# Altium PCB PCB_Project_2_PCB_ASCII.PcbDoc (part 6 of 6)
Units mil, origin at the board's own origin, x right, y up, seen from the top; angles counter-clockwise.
Board outline 3900 x 7800 mil, 6 copper layers (Top Layer, GND 1, Signal, Power, GND 2, Bottom Layer), stack 62.1 mil thick; 636 components, 334 nets, 1830 pads, 1401 vias.
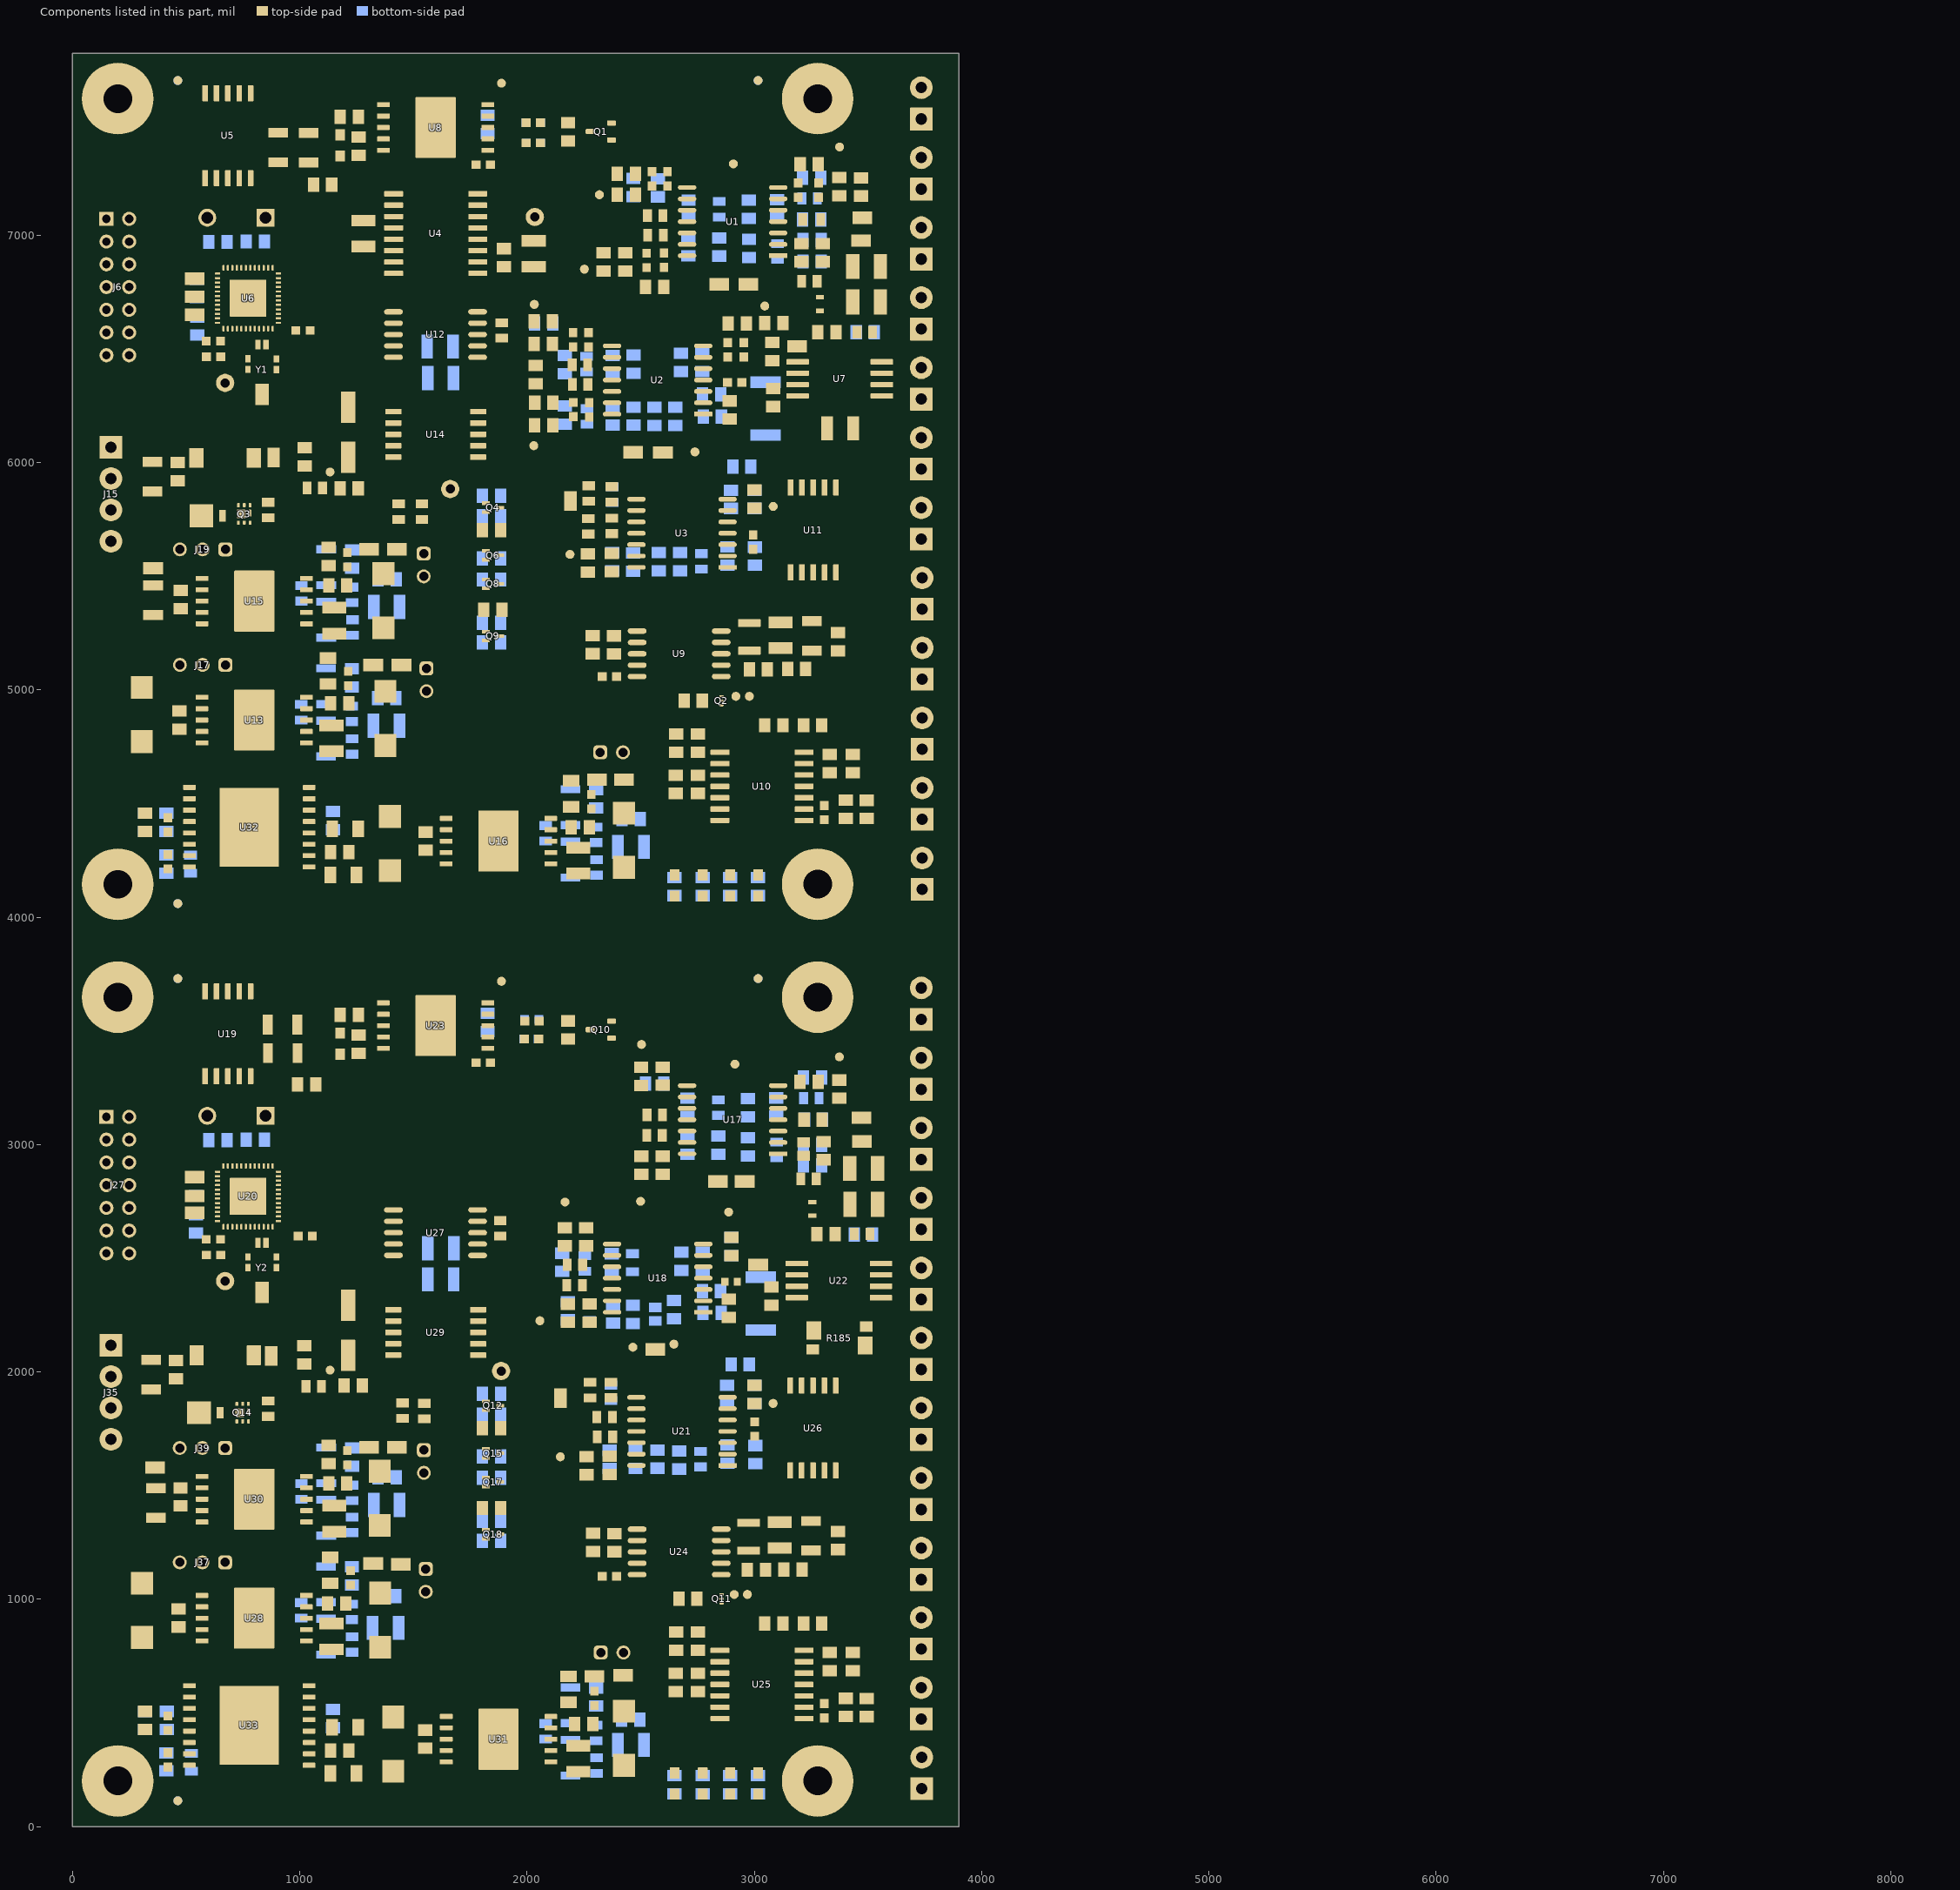
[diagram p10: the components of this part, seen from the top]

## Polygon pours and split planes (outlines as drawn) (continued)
Vcc(m) on Bottom Layer "Bottom Layer-Vcc(m) 1" (solid, pour order 1098): 2824,2077 2916,2077 2929,2064 2929,1997 2918,1986 2819,1986 2801,2004 2801,2063 2815,2077
P5V0(m) on Bottom Layer "Bottom Layer-P5V0(m)" (solid, pour order 1102): 2842.73,1627.66 2917.09,1627.66 2938.43,1606.32 2938.43,1521.93 2919.5,1503 2858.08,1503 2830.6,1530.49 2830.6,1614.29 2842.73,1626.42
Vcc(m) on Bottom Layer "Bottom Layer-Vcc(m)" (solid, pour order 1104): 2487.71,992.4 2395.34,992.4 2362.82,1024.92 2362.82,1149.9 2432.65,1219.73 2432.65,1503.07 2432.65,1593.56 2445.41,1606.32 2507.48,1606.32 2518.65,1595.16 2518.65,1505.64 2518.65,1023.34
P3V3(m) on Bottom Layer "Bottom Layer-P3V3 2" (solid, pour order 1052): 586.6,2826.86 501.86,2826.87 494.62,2834.1 494.62,2877.67 494.62,3053.31 510.22,3068.91 619.5,3068.91 634.24,3054.16 634.24,2977.38 593.41,2936.55 593.41,2887.73 593.41,2833.67
Vcc(x) on Bottom Layer "Bottom Layer-Vcc(x)" (solid, pour order 1132): 788.45,5772.8 1396.38,5772.8 1418.04,5751.13 1418.04,5693.51 1390.91,5666.37 722.72,5666.37 515.64,5873.46 113.54,5873.46 98,5889 98,5969 120,5991 568.54,5991
P2V5 on Bottom Layer "Bottom Layer-P2V5" (solid, pour order 1110): 73 vertices, not listed, extent 861.42,2272.65 3524.98,3584.86
GND on Bottom Layer "GND-GND" (solid, pour order 1152): 12.86,7692.78 12.86,4052.5 96.94,3968.42 3774.01,3968.42 3875.54,4069.96 3875.54,7746.23 3830.41,7791.36 111.44,7791.36
GND(m) on Bottom Layer "GND-GND(m)" (solid, pour order 1154): 31.47,3788.16 78.87,3835.56 3850.05,3835.56 3888.03,3797.58 3888.03,72.55 3835.6,20.12 61.99,20.12 31.47,50.64
Vee(x) on Signal "Layer 3-Vee(x)" (solid, pour order 560): 1774.99,5403.31 1803.7,5374.6 1803.7,5191.52 1773.84,5161.92 94.24,5161.92 68.43,5187.72 68.43,5812.15 108.48,5852.19 546.99,5852.19 995.87,5403.31
Vcc on Signal "Layer 3-Vcc" (solid, pour order 556): 21 vertices, not listed, extent 1888.24,5262.46 2977.65,6462.45
Vcc(m) on Signal "Layer 3-Vcc" (solid, pour order 1082): 19 vertices, not listed, extent 1888.02,1318.59 2975.15,2483.07
Vee(mx) on Signal "Layer 3-Vee(x)" (solid, pour order 1084): 1782.47,1245.54 1742.87,1204.16 105.58,1204.16 53.79,1255.95 53.79,1861.06 93.84,1901.1 532.35,1901.1 981.23,1452.22 1721.48,1452.22 1782.47,1391.24
P5V0(m,Op) on Signal "Layer 3-P5V0(Op)" (solid, pour order 1080): 26 vertices, not listed, extent 1048.23,110.66 3640.82,3182.43
P5V0(Op) on Signal "Layer 3-P5V0(Op)" (solid, pour order 558): 26 vertices, not listed, extent 1048.54,4046.74 3641.13,7156.11
NetC12_1 on Power "Power-NetC11_1" (solid, pour order 1142): 936.31,7252.76 1008.89,7252.75 1036.05,7225.6 1036.05,6631.27 1006.59,6601.81 923.66,6601.81 897.3,6628.17 897.3,7213.75
Vee(m) on Power "Layer 4-Vee" (solid, pour order 1062): 2486.32,3189.34 2514.41,3161.25 2514.41,3012.02 2514.41,2866.28 2338.8,2690.68 2338.8,1285.61 2285.7,1232.51 1955.79,1232.51 1913.36,1274.95 1913.36,2966 2136.69,3189.34
P5V0(m) on Power "Layer 4-P5V0" (solid, pour order 1066): 18 vertices, not listed, extent 75.36,115.67 3509.31,2195.26
P3V3(b) on Power "Layer 4-P3V3(b)" (solid, pour order 566): 20 vertices, not listed, extent 1087.53,4568.07 2365.95,7248.25
P3V3 on Power "Layer 4-P3V3" (solid, pour order 562): 23 vertices, not listed, extent 195.4,4770 1945.89,7617.97
P3V3(mb) on Power "Layer 4-P3V3(b)" (solid, pour order 1064): 19 vertices, not listed, extent 1032.29,623.58 2365.95,3283.28
P5V0 on Power "Layer 4-P5V0" (solid, pour order 568): 19 vertices, not listed, extent 75.36,4056.12 3499.49,6948.59
Vee on Power "Layer 4-Vee" (solid, pour order 564): 2489.91,7044.58 2516.15,7018.34 2516.15,6890.35 2358,6732.19 2358,5732.32 2358.99,5731.32 2358.99,5225.05 2310.95,5177 1955.79,5177 1916.33,5216.47 1916.33,6893.83 2067.08,7044.58
P3V3(m) on Power "Layer 4-P3V3" (solid, pour order 1068): 21 vertices, not listed, extent 202.03,807.46 1952.52,3672.39
GND on GND 1 "GND-GND" (solid, pour order 548): 12.86,7692.78 12.86,4052.5 95.35,3970.01 3775.6,3970.01 3875.54,4069.96 3875.54,7746.23 3830.41,7791.36 111.44,7791.36
GND(m) on GND 1 "GND-GND(m)" (solid, pour order 1078): 31.47,3788.16 78.87,3835.56 3850.05,3835.56 3888.03,3797.58 3888.03,72.55 3835.6,20.12 61.99,20.12 31.47,50.64
GND on GND 2 "VCC-GND" (solid, pour order 570): 108.49,7787.04 12.86,7691.41 12.86,4052.5 95.71,3969.65 3775.24,3969.65 3875.54,4069.96 3875.54,7746.23 3830.41,7791.36 113.92,7791.36 111.22,7788.66
GND(m) on GND 2 "GND-GND(m)" (solid, pour order 1108): 31.47,3788.16 78.87,3835.56 3850.05,3835.56 3888.03,3797.58 3888.03,72.55 3835.6,20.12 61.99,20.12 31.47,50.64

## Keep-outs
Keep-Out Layer:
  text ".Layer_Name" at 577,-858.49 h60

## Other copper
Top Layer:
  text ".Layer_Name" at 577,-858.49 h60
Signal:
  text "Signal layer" at 723.95,-842.08 h60
Power:
  text "Power layer" at 807.51,-851.37 h60
GND 1:
  text "GND1" at 689.91,-851.37 h60
GND 2:
  text "GND 2" at 717.76,-851.37 h60
Bottom Layer:
  text ".Layer_Name" at 577,-858.49 h60

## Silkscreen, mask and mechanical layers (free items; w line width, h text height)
Top Overlay:
  lines w10: 1187.8,7229.5 1187.8,7258.04 1311.08,7258.04 1311.08,7352.78 ; 7.49,370.03 376.46,370.03 376.46,152.55 2542.49,152.55 2542.49,923.06 1982.35,923.06 1982.35,1940 1360,1940 1360,2380.24 1058.28,2380.24 1058.28,2249.31 7.49,2249.31 7.49,370.03 ; 7.62,4318.98 7.62,6201.26 1057.97,6201.26 1057.97,6332.19 1365,6332.19 1365,5960 1944.19,5960 1944.19,4871.11 2542.62,4871.11 2542.62,4099.24 372.91,4099.24 372.91,4318.98 7.62,4318.98 ; 1205.5,6747.43 2121.46,6747.43 2121.46,7238.18 1205.5,7238.18 1205.5,6747.43 ; 1962.91,4895.89 3623.03,4895.89 3623.03,7430.32 2442.77,7430.32 2442.77,7326.58 2139.26,7326.58 2139.26,7237.19 2139.26,6728.46 1962.91,6728.46 1962.91,4895.89 ; 2002.48,943.94 2002.48,2824.35 2434.93,2824.35 2434.93,3216.03 2434.93,3362.21 2434.93,3477.3 3616.95,3477.3 3616.95,943.94 2002.48,943.94
  text "TMP461" at 1497.66,7642.24 h60
  text "D-" at 3539.41,7586.93 h60
  text "D+" at 3539.41,7517.24 h60
  text "20V" at 3559.77,7366.37 h60 r270
  text "SIGNAL CHAIN" at 2507.14,7351.52 h100
  text "U1 Out" at 2955,7302.26 h60
  text "GND" at 3561.35,7255.58 h60 r270
  text "1.TDO" at 388.38,7237.05 h60
  text "3.TDI" at 388.38,7171.18 h60
  text "500uA" at 3535.38,7109.04 h60 r270
  text "4.P3V3" at 388.38,7105.3 h60
  text "5.TMS" at 388.38,7039.42 h60
  text "7.TCk" at 388.38,6973.49 h60
  text "9.GND" at 388.38,6907.67 h60
  text "MSP430FR5969" at 570.23,6896.66 h60
  text "ADC128S102" at 1467.65,6758.39 h60
  text "DAC121S101" at 1466.7,6367.48 h60
  text "+/-5V" at 3475.44,6172.47 h60
  text "+/-2A X" at 3411.33,6012.39 h60
  text "+/-2A Y" at 3412.07,5953.3 h60
  text "Current" at 3402.53,5786.95 h40
  text "Sense Bus" at 3402.53,5749.84 h40
  text "Current" at 3402.53,5681.62 h40
  text "Sense Load" at 3402.53,5642.09 h40
  text "Vcc(y)" at 1618.87,5637.76 h60 r270
  text "1.P5V0" at 47.51,5495.69 h60
  text "40V" at 3504.58,5465.64 h60
  text "2.Vcc(x)" at 47.51,5414.26 h60
  text "GND" at 3484.07,5328.83 h60
  text "3.Vee(x)" at 47.51,5322.23 h60
  text "4.GND" at 47.51,5219.59 h60
  text "P3V3" at 1504.54,5164.07 h60
  text "5V" at 3535.72,5160.09 h60
  text "GND" at 3488.02,5028.01 h60
  text "POWER" at 1575.35,4838.45 h100
  text "Fixed" at 3444.97,4834.14 h40
  text "Current Source" at 3358.7,4800.5 h40
  text "P3V3(b)" at 2269.73,4797.93 h60
  text "Voltage Source" at 3551.67,4596.51 h40 r270
  text "Adjustable" at 3590.68,4596.98 h40 r270
  text "Adjustable" at 3434.59,4218.29 h40
  text "Current" at 3447.31,4178.21 h40
  text "Source" at 3449.22,4141.32 h40
  text "TMP461" at 1497.66,3692.24 h60
  text "D+" at 3544.48,3629.9 h60
  text "D-" at 3544.48,3556.28 h60
  text "1.2TDO" at 284.5,3467.27 h60
  text "3.2TDI" at 286.32,3410.85 h60
  text "SIGNAL CHAIN" at 2668.81,3393.01 h100
  text "4.P3V3(m)" at 284.26,3355.42 h60
  text "20V(i)" at 3464.61,3317.83 h60
  text "GND(m)" at 3471.45,3268.83 h40
  text "500uA" at 3567.57,3135.5 h60 r270
  text "5.2TMS" at 395.48,3045.57 h60
  text "7.2TCk" at 392.73,2993.41 h60
  text "MSP430FR5969" at 647.15,2958.54 h60
  text "9.GND(m)" at 386.34,2940.71 h60
  text "'.PRJ_Number'.PCB_Rev" at 1859.93,2933.74 h39.37
  text "DAC121S101" at 1466.7,2417.48 h60
  text "+/-5V" at 3566.08,2286.75 h60 r270
  text "+/-2A X" at 3425.11,2008.18 h60
  text "+/-2A Y" at 3424.2,1955.39 h60
  text "Current" at 3410.69,1826.43 h40
  text "Sense Bus" at 3410.69,1786.4 h40
  text "Current" at 3406.99,1712.72 h40
  text "Sense Load" at 3406.99,1672.92 h40
  text "1.P5V0(m)" at 21.41,1538.86 h60
  text "40V(i)" at 3434.95,1504.01 h60
  text "2.Vcc(m,x)" at 21.41,1457.86 h60
  text "3.Vee(mx)" at 21.41,1376.85 h60
  text "GND(m)" at 3404.82,1353.95 h60
  text "4.GND(m)" at 21.41,1295.85 h60
  text "5V(i)" at 3490.57,1194.04 h60
  text "GND(m)" at 3403.66,1061.94 h60
  text "POWER" at 1630.38,977.32 h100
  text "Fixed" at 3426.79,897.01 h40
  text "Current Source" at 3349.74,850.41 h40
  text "Voltage Source" at 3549.71,642.69 h40 r270
  text "Adjustable" at 3588.82,641.59 h40 r270
  text "Adjustable" at 3430.35,266.9 h40
  text "Current" at 3452.94,227.75 h40
  text "Source" at 3452.94,186.21 h40
  text ".Layer_Name" at 577,-858.49 h60
Bottom Overlay:
  text ".Layer_Name" at 577,-858.49 h60
Top Paste:
  text ".Layer_Name" at 577,-858.49 h60
Bottom Paste:
  text ".Layer_Name" at 577,-858.49 h60
Top Solder:
  text ".Layer_Name" at 577,-858.49 h60
  text ".Layer_Name" at 577,-858.49 h60
Bottom Solder:
  text ".Layer_Name" at 577,-858.49 h60
Drill Guide:
  text ".Layer_Name" at 577,-858.49 h60
M1 Board Outline:
  lines w10: 0,3900 3900,3900 ; 2219,0 2219.09,0 ; 3900,-0.85 3900,7799.15 ; 3900,0 0,0 0,7800 3900,7800 ; 3956.85,3938.67 3918.29,3900.11 ; 3957.45,3860.96 3918.29,3900.11 ; 4174.41,3900.11 3918.29,3900.11
  text "NOTE A" at 4219.77,3871.07 h100
  text ".Layer_Name" at 577,-858.49 h60
M2 Board Dimensions:
  rectangle: 0,-275 125,-150
  rectangle: 125,-400 500,-275
  lines w7: 0,-275 1000,-275 ; 125,-400 125,-150 ; 250,-400 250,-150 ; 500,-400 500,-150 ; 750,-400 750,-150 ; 0,-400 1000,-400 1000,-150 0,-150 0,-400
  text ".Layer_Name" at 577,-858.49 h60
M3 3D STEP Top:
  text ".Layer_Name" at 577,-858.49 h60
M4 3D STEP Bottom:
  text ".Layer_Name" at 577,-858.49 h60
M5 Assembly Top:
  lines w10: -292,-930.17 6308,-930.17 ; -292,-726.83 6310,-726.83 ; -292,-523.5 -292,-1133.5 3713,-1133.5 6310,-1133.5 6310,-523.5 -291.5,-523.5 -291.5,-1133.5 1284,-1133.5 ; 2173,-1133.5 2173,-523.5 ; 3440,-726.83 3440,-523.5 ; 4280,-726.83 4280,-523.5 ; 4902,-1140 4902,-937.17
  text "COMPONENTS MARKED 'DNP' SHOULD NOT BE POPULATED." at 1153.5,-318.5 h60
  text "ASSEMBLY VARIANT:" at 1153,-434 h60
  text ".VariantName" at 2189,-434 h60
  text "PCB VIEWED FROM TOP SIDE" at -228.5,-655.67 h60
  text "BOARD #:" at 2248,-655.67 h60
  text ".PRJ_Number" at 2793.5,-655.67 h60
  text "REV:" at 3638,-655.67 h60
  text ".PCB_Rev" at 3929.5,-655.67 h60
  text "SVN REV:" at 4476,-655.67 h60
  text ".VersionControl_RevNumber" at 4982,-655.67 h60
  text "Assembly top" at 447.68,-836.36 h60
  text "TID #:" at 2248,-859 h60
  text ".TID" at 2793.5,-859 h60
  text "PLOT NAME =" at -228.5,-1064.34 h60
  text ".plot_File_Name" at 577,-1064.34 h60
  text "GENERATED    :" at 2250,-1064.34 h40
  text ".Print_Date" at 3119.5,-1064.34 h60
  text ".Print_Time" at 3848.5,-1064.34 h60
  text "TEXAS INSTRUMENTS" at 5113,-1064.34 h60
M6 Assembly Bottom:
  lines w10: -292.5,-727.33 6309.5,-727.33 ; -290.5,-930.67 6309.5,-930.67 ; 1115.5,-1140.5 1115.5,-937.67 ; 1737.5,-727.33 1737.5,-524 ; 2577.5,-727.33 2577.5,-524 ; 3844.5,-1134 3844.5,-524 ; 4733.5,-1134 6309,-1134 6309,-524 -292.5,-524 -292.5,-1134 2304.5,-1134 6309.5,-1134 6309.5,-524
  text "COMPONENTS MARKED 'DNP' SHOULD NOT BE POPULATED." at 6102,-318 h60
  text ".VariantName" at 5058,-434 h60
  text "ASSEMBLY VARIANT:" at 6097,-434 h60
  text ".VersionControl_RevNumber" at 1035.5,-656.17 h60
  text "SVN REV:" at 1541.5,-656.17 h60
  text ".PCB_Rev" at 2088,-656.17 h60
  text "REV:" at 2379.5,-656.17 h60
  text ".PRJ_Number" at 3224,-656.17 h60
  text "BOARD #:" at 3769.5,-656.17 h60
  text "PCB VIEWED FROM BOTTOM SIDE" at 6246,-656.17 h60
  text "Assembly bottom" at 6178.79,-845.68 h60
  text ".TID" at 3224,-859.5 h60
  text "TID #:" at 3769.5,-859.5 h60
  text "TEXAS INSTRUMENTS" at 904.5,-1064.84 h60
  text ".Print_Time" at 2169,-1064.84 h60
  text ".Print_Date" at 2898,-1064.84 h60
  text "GENERATED    :" at 3767.5,-1064.84 h60
  text ".plot_File_Name" at 5440.5,-1064.84 h60
  text "PLOT NAME =" at 6246,-1064.84 h60
M9 Title Sheet:
  lines w10: -491.5,1041.5 -291.5,1041.5 ; -491.5,3416.5 -291.5,3416.5 ; -491.5,5791.5 -291.5,5791.5 ; 2008.5,-1333.5 2008.5,-1133.5 ; 2008.5,7966.5 2008.5,8166.5 ; 4508.5,-1333.5 4508.5,-1133.5 ; 4508.5,7966.5 4508.5,8166.5 ; 6321,-1133.5 6321,-523.5 11303.5,-523.5 ; 7008.5,-1333.5 7008.5,-1133.5 ; 7008.5,7966.5 7008.5,8166.5 ; 9508.5,-1333.5 9508.5,-1133.5 ; 9508.5,7966.5 9508.5,8166.5 ; 11303.5,-1133.5 11303.5,-523.5 ; 11303.5,-823.5 14303.5,-823.5 ; 11303.5,-223.5 14303.5,-223.5 ; 11304.5,370.5 14304.5,370.5 ; 12008.5,-1333.5 12008.5,-1133.5 ; 12008.5,7966.5 12008.5,8166.5 ; 12808.5,-1123.5 12808.5,-523.5 ; 14303.5,-523.5 11303.5,-523.5 ; 14303.5,76.5 11303.5,76.5 ; 14308.5,66.5 14308.5,-1133.5 ; 14308.5,871 11304.5,871 11303.5,871 11303.5,370.5 11303.5,76.5 ; 14308.5,1041.5 14508.5,1041.5 ; 14308.5,3416.5 14508.5,3416.5 ; 14308.5,5791.5 14508.5,5791.5 ; 11303.5,-523.5 11303.5,76.5 ; 14308.5,-1133.5 14308.5,7966.5 -291.5,7966.5 -291.5,-1133.5 14308.5,-1133.5 ; -491.5,-1333.5 -491.5,8166.5 14508.5,8166.5 14508.5,-1333.5 -491.5,-1333.5
  text "1" at 739.84,8036.5 h60
  text "2" at 3235.5,8036.5 h60
  text "3" at 5724.84,8036.5 h60
  text "4" at 8231.51,8036.5 h60
  text "5" at 10730.5,8036.5 h60
  text "6" at 13235.5,8036.5 h60
  text "A" at -416.5,6893.5 h60
  text "A" at 14383.5,6893.5 h60
  text "B" at -416.5,4513.5 h60
  text "B" at 14383.5,4513.5 h60
  text "C" at -416.5,2138.5 h60
  text "C" at 14383.5,2138.5 h60
  text "PROJECT TITLE:" at 11343.5,277.5 h60
  text ".PRJ_Title" at 11393.5,144.17 h60
  text "DESIGNED FOR:" at 11343.5,-23.5 h60
  text ".PRJ_Customer" at 11393.5,-163.5 h60
  text "D" at -416.5,-231.5 h60
  text "D" at 14383.5,-231.5 h60
  text "FILE NAME:" at 11343.5,-323.5 h60
  text ".PCB_File_Name_No_Path" at 11393.5,-443.5 h60
  text "Texas Instruments (TI) and/or its licensors do not warrant the accuracy or completeness of this specification" at 6374,-605.34 h45
  text "ENGINEER:" at 11343.5,-613.5 h60
  text "LAYOUT BY:" at 12848.5,-613.5 h60
  text "or any information contained therein. TI and/or its licensors do not warrant that this design will meet" at 6329.01,-718 h45
  text ".PRJ_Engineer" at 11393.5,-768.49 h60
  text ".PCB_Layout" at 12899,-768.49 h60
  text "the specifications, will be suitable for your application or fit for any particular purpose, or will operate in" at 6329.01,-830.67 h45
  text ".Layer_Name" at 577,-858.49 h60
  text "ALTIUM DESIGNER VERSION:" at 12848.5,-923.5 h60
  text "an implementation. TI and/or its licensors do not warrant that the design is production worthy. You should" at 6329.01,-943.33 h45
  text "completely validate and test your design implementation to confirm the system functionality for your application." at 6374,-1056 h45
  text ".print_Scale" at 11393.5,-1056.83 h60
  text ".Application_BuildNumber" at 12899,-1056.83 h60
  text "1" at 739.84,-1263.5 h60
  text "2" at 3235.5,-1263.5 h60
  text "3" at 5724.84,-1263.5 h60
  text "4" at 8231.51,-1263.5 h60
  text "5" at 10730.5,-1263.5 h60
  text "6" at 13235.5,-1263.5 h60
M10 Fab Notes:
  drawing of 189 lines, arcs and shapes, not listed
  text "NOTE A :" at 4760.83,6386.73 h60
  text "DESIGN INFORMATION" at 12382.02,6356.17 h60
  text "MIN. TRACK WIDTH:" at 11737.46,6224.05 h60
  text "MIL" at 12988.46,6224.05 h60
  text "6.5" at 12795.99,6221.67 h60
  text "V_Score is required at the mentioned location in between the two boards." at 4770.13,6206.88 h60
  text "MIN. CLEARANCE:" at 11737.46,6099.92 h60
  text "0.2" at 12773.7,6099.93 h60
  text "mm" at 12988.46,6099.92 h60
  text "MIN. VIA PAD SIZE:" at 11737.46,5975.8 h60
  text "20" at 12803.71,5975.8 h60
  text "MIL" at 12988.46,5975.8 h60
  text "MINIMUM ANNULAR RING" at 11408.23,5837.67 h60
  text "0.05mm (2MIL)" at 12594,5835.93 h60
  text "EXTERNAL" at 13340.5,5831.16 h60
  text "PER" at 11608.23,5727.55 h60
  text "IPC-D-275 CLASS 2 LEVEL C" at 11828.23,5727.54 h60
  text "MIL,HOLES" at 13316.46,5627.07 h60
  text "+/-" at 12924,5618.48 h60
  text "+/-" at 13778,5618.48 h60
  text "REGISTRATION TOLERANCES:" at 11408.23,5617.42 h60
  text "METAL" at 12608,5617.42 h60
  text "5" at 13184.2,5617.42 h60
  text "3" at 14017.2,5617.42 h60
  text "MIL" at 14133.46,5617.42 h60
  text "HOLE SIZE TOLERANCE (UNLESS OTHERWISE SPECIFIED):" at 11408.23,5519.1 h60
  text "+/-" at 13778,5516.23 h60
  text "3" at 14017.2,5515.17 h60
  text "MIL" at 14133.46,5515.17 h60
  text "MATERIAL:" at 11333.46,5377.52 h60
  text "FR-4 High Tg" at 12319.9,5249 h60
  text "X" at 12175.46,5241.01 h60
  text "FR-408" at 11754.46,5236.49 h60
  text "OTHER" at 13242.46,5236.49 h60
  text "THICKNESS:" at 11345.92,5107.04 h60
  text "62 MIL(1.6mm)+/-10%" at 12074.56,5093.46 h60
  text "X" at 11954.46,5091.01 h60
  text "OTHER" at 13359.46,5085.24 h60
  text "TOLERANCE:" at 11408.23,4946.92 h60
  text "X" at 12256.46,4946.92 h60
  text "ANSI IPC-6012 TYPE 3 CLASS 2" at 12434.48,4946.92 h60
  text "OTHER +/-" at 12434.46,4802.73 h60
  text "BOW & TWIST:" at 11408.23,4657.54 h60
  text "X" at 12256.46,4657.54 h60
  text "ANSI IPC-6012 TYPE 3 CLASS 2" at 12434.48,4657.54 h60
  text "OTHER +/-" at 12434.46,4510.85 h60
  text "DRILLING:" at 11333.46,4380.23 h60
  text "NC_DRILL FILES" at 13094.46,4275.04 h60
  text "REFERENCE:" at 11408.23,4271.1 h60
  text "X" at 12065.46,4271.01 h60
  text "AS SHOWN" at 12243.46,4271.1 h60
  text "X" at 12966.46,4271.1 h60
  text "OTHER" at 13392.46,4128.85 h60
  text "PTH COPPER THICKNESS:" at 11407.91,4125.32 h60
  text "X" at 12547.14,4125.32 h60
  text "20-30 um" at 12675.14,4125.32 h60
  text "BOARD FINISH:" at 11333.46,3977.73 h60
  text "SILKSCREEN:" at 11488.68,3867.6 h60
  text "X" at 12446.46,3867.6 h60
  text "TOP" at 12563.46,3867.6 h60
  text "X" at 12956.46,3867.6 h60
  text "BOTTOM" at 13074.46,3867.6 h60
  text "SILKSCREEN COLOR:" at 11488.68,3712.41 h60
  text "X" at 12445.46,3712.41 h60
  text "WHITE" at 12563.46,3712.41 h60
  text "OTHER" at 13074.46,3712.41 h60
  text "X" at 12576.46,3568.96 h60
  text "GREEN" at 12694.46,3568.96 h60
  text "OTHER" at 13312.46,3568.96 h60
  text "SOLDER RESIST COLOR:" at 11488.68,3562.1 h60
  text "X" at 12576.46,3414.71 h60
  text "MATTE" at 12694.46,3414.71 h60
  text "SEMI-GLOSS" at 13312,3414.07 h60
  text "IMMERSION GOLD (ENIG)" at 12394.46,3241.94 h60
  text "ENEPIG" at 13732,3234.72 h60
  text "SURFACE FINISH:" at 11333.46,3233.72 h60
  text "X" at 12216.46,3233.72 h60
  text "IMM. TIN/SILVER OR EQUIV" at 11663,3096.4 h60
  text "OTHER" at 13094.46,3092.47 h60
  text "ARRAY/PANEL:" at 11333.46,2937.09 h60
  text "CUT AND TRIM PER M1 BOARD OUTLINE" at 12394.46,2928.87 h60
  text "N.C. ROUTE" at 12394.46,2792.9 h60
  text "X" at 13082.46,2792.9 h60
  text "V. SCORE" at 13260.46,2792.9 h60
  text "CERTIFICATION:" at 11333.46,2663.77 h60
  text "MATERIALS AND WORKMANSHIP FOR ALL PCBS" at 12058.46,2663.77 h60
  text "TO MEET OR EXCEED THE REQUIREMENTS OF:" at 12058.46,2569.71 h60
  text "X" at 11695.97,2441.08 h60
  text "ANSI IPC-A-600F CLASS->" at 11823.96,2441.08 h60
  text "X" at 13471.97,2441.08 h60
  text "2" at 13581.96,2441.08 h60
  text "1" at 13266.96,2439.58 h60
  text "3" at 13935.96,2439.58 h60
  text "X" at 12507.97,2293.39 h60
  text "RoHS" at 12635.96,2293.39 h60
  text "OTHER" at 13280.36,2293.39 h60
  text "PER ORDER" at 13677.42,2293.39 h60
  text "ALL BOARDS MUST MEET OR EXCEED UL94-V0 REQUIREMENTS." at 11361,2139.57 h60
  text "PCB MUST BEAR THE UL94V-0 UL REGISTERED MATERIAL ID NUMBER" at 11361,2023.5 h60
  text "ADDITIONAL REQUIREMENTS:" at 11333.46,1854.08 h60
  text "MICROSECTION:" at 11408.23,1746.95 h60
  text "YES" at 12313.96,1746.95 h60
  text "REQUIRED" at 13175.46,1602.62 h60
  text "BARE BOARD ELEC. TEST:" at 11408.23,1599.76 h60
  text "NONE" at 12713.96,1599.76 h60
  text "X" at 13057.46,1599.76 h60
  text "PER ORDER" at 13767.46,1599.76 h60
  text "XX MIL VIAS REQUIRE NON-CONDUCTIVE FILL AND PLANARIZE" at 11385.93,1355.83 h60
  text "XX MIL VIAS REQUIRE CONDUCTIVE FILL AND PLANARIZE" at 11603.46,1279.09 h60
  text "OUTER 7.5 MIL TRACES REQUIRE 50 OHM SINGLE-ENDED IMPEDANCE" at 11600.05,1164.68 h60
  text "X" at 11463.33,1133.07 h60
  text "LAYER 2 & 3 (INNER LAYERS) XX MIL WIDE,XX MIL SPACE / TRACES REQUIRE 100 OHM DIFFERENTIAL IMPEDANCE" at 11577.17,832.89 h60
  text ".Layer_Name" at 577,-858.49 h60
M11 Gerber Information:
  lines w10: -292,-930.17 6308,-930.17 ; -292,-726.83 6310,-726.83 ; -292,-523.5 -292,-1133.5 3713,-1133.5 6310,-1133.5 6310,-523.5 -291.5,-523.5 -291.5,-1133.5 1284,-1133.5 ; 2173,-1133.5 2173,-523.5 ; 3440,-726.83 3440,-523.5 ; 4280,-726.83 4280,-523.5 ; 4902,-1140 4902,-937.17
  text "ALL ARTWORK VIEWED FROM TOP SIDE" at -228.5,-655.67 h60
  text "BOARD #:" at 2248,-655.67 h60
  text ".PRJ_Number" at 2793.5,-655.67 h60
  text "REV:" at 3638,-655.67 h60
  text ".PCB_Rev" at 3929.5,-655.67 h60
  text "SVN REV:" at 4476,-655.67 h60
  text ".VersionControl_RevNumber" at 4982,-655.67 h60
  text "LAYER NAME =" at -228.5,-858.49 h60
  text "TID #:" at 2248,-859 h60
  text ".TID" at 2793.5,-859 h60
  text "PLOT NAME =" at -228.5,-1064.34 h60
  text ".plot_File_Name" at 577,-1064.34 h60
  text "GENERATED    :" at 2250,-1064.34 h60
  text ".Print_Date" at 3119.5,-1064.34 h60
  text ".Print_Time" at 3848.5,-1064.34 h60
  text "TEXAS INSTRUMENTS" at 5113,-1064.34 h60
M12 Stackup:
  drawing of 399 lines, arcs and shapes, not listed
  text "Layer" at 6642.88,5511.01 h60
  text "Name" at 7052.79,5511.01 h60
  text "Material" at 7982.54,5511.01 h60
  text "Thickness" at 8842.3,5511.01 h60
  text "Constant" at 9492.14,5511.01 h60
  text "Board Layer Stack" at 10062,5511.01 h60
  text "Top Overlay" at 7052.79,5391.01 h60
  text "Top Solder" at 7052.79,5271.01 h60
  text "Solder Resist" at 7982.54,5271.01 h60
  text "0.40mil" at 8842.3,5271.01 h60
  text "3.5" at 9492.14,5271.01 h60
  text "1" at 6642.88,5151.01 h60
  text "Top Layer" at 7052.79,5151.01 h60
  text "1.40mil" at 8842.3,5151.01 h60
  text "Dielectric 1" at 7052.79,5031.01 h60
  text "PP-006" at 7982.54,5031.01 h60
  text "5.00mil" at 8842.3,5031.01 h60
  text "4.1" at 9492.14,5031.01 h60
  text "2" at 6642.88,4911.01 h60
  text "GND 1" at 7052.79,4911.01 h60
  text "1.38mil" at 8842.3,4911.01 h60
  text "Dielectric 3" at 7052.79,4791.01 h60
  text "PP-006" at 7982.54,4791.01 h60
  text "6.00mil" at 8842.3,4791.01 h60
  text "4.1" at 9492.14,4791.01 h60
  text "3" at 6642.88,4671.01 h60
  text "Signal" at 7052.79,4671.01 h60
  text "1.38mil" at 8842.3,4671.01 h60
  text "Dielectric1" at 7052.79,4551.01 h60
  text "FR-4" at 7982.54,4551.01 h60
  text "31.79mil" at 8842.3,4551.01 h60
  text "4.8" at 9492.14,4551.01 h60
  text "4" at 6642.88,4431.01 h60
  text "Power" at 7052.79,4431.01 h60
  text "1.38mil" at 8842.3,4431.01 h60
  text "Dielectric 4" at 7052.79,4311.01 h60
  text "PP-006" at 7982.54,4311.01 h60
  text "6.00mil" at 8842.3,4311.01 h60
  text "4.1" at 9492.14,4311.01 h60
  text "5" at 6642.88,4191.01 h60
  text "GND 2" at 7052.79,4191.01 h60
  text "1.38mil" at 8842.3,4191.01 h60
  text "Dielectric 2" at 7052.79,4071.01 h60
  text "PP-006" at 7982.54,4071.01 h60
  text "5.00mil" at 8842.3,4071.01 h60
  text "4.1" at 9492.14,4071.01 h60
  text "6" at 6642.88,3951.01 h60
  text "Bottom Layer" at 7052.79,3951.01 h60
  text "1.40mil" at 8842.3,3951.01 h60
  text "Bottom Solder" at 7052.79,3831.01 h60
  text "Solder Resist" at 7982.54,3831.01 h60
  text "0.40mil" at 8842.3,3831.01 h60
  text "3.5" at 9492.14,3831.01 h60
  text "Bottom Overlay" at 7052.79,3711.01 h60
  text ".Layer_Name" at 577,-858.49 h60
M13 Component Bodies Top:
  text ".Layer_Name" at 577,-858.49 h60
M14 Component Bodies Bottom:
  text ".Layer_Name" at 577,-858.49 h60
M15 Courtyards Top:
  text ".Layer_Name" at 577,-858.49 h60
M16 Courtyards Bottom:
  text ".Layer_Name" at 577,-858.49 h60
Drill Drawing:
  circle w10: c5614.47,2546.76 r28.68
  lines w10: 5585.79,2647.13 5585.79,2661.47 5600.13,2675.81 5585.79,2690.15 5585.79,2704.49 5600.13,2704.49 5614.47,2690.15 5628.81,2704.49 5643.15,2704.49 5643.15,2690.15 5628.81,2675.81 5643.15,2661.47 5643.15,2647.13 5628.81,2647.13 5614.47,2661.47 5600.13,2647.13 5585.79,2647.13 ; 5585.79,2776.18 5643.15,2776.18 5643.15,2833.54 5585.79,2833.54 5585.79,2776.18 ; 5585.79,2919.57 5600.13,2919.57 5614.47,2905.24 5628.81,2919.57 5643.15,2919.57 5628.81,2933.91 5643.15,2948.25 5628.81,2948.25 5614.47,2962.59 5600.13,2948.25 5585.79,2948.25 5600.13,2933.91 5585.79,2919.57 ; 5585.79,3034.29 5643.15,3034.29 5643.15,3091.64 5585.79,3091.64 5585.79,3034.29 ; 5585.79,3177.68 5600.13,3177.68 5600.13,3163.34 5628.81,3163.34 5628.81,3177.68 5643.15,3177.68 5643.15,3206.36 5628.81,3206.36 5628.81,3220.7 5600.13,3220.7 5600.13,3206.36 5585.79,3206.36 5585.79,3177.68 ; 5585.79,3349.75 5643.15,3349.75 5614.47,3292.39 5585.79,3349.75 ; 5585.79,3450.12 5614.47,3421.44 5643.15,3450.12 5614.47,3478.8 5585.79,3450.12 ; 5597.26,3045.76 5631.68,3045.76 5631.68,3080.17 5597.26,3080.17 5597.26,3045.76
  lines w12: 5533.92,2479.36 11078.59,2479.36 ; 5533.92,3511.78 11078.59,3511.78 ; 6012.33,2350.31 6012.33,3640.83 ; 6574.2,2350.31 6574.2,3640.83 ; 7736.35,2350.31 7736.35,3640.83 ; 8176.05,2350.31 8176.05,3640.83 ; 8811.84,2350.31 8811.84,3640.83 ; 10104.77,2350.31 10104.77,3640.83 ; 5533.92,2350.31 11078.59,2350.31 11078.59,3640.83 5533.92,3640.83 5533.92,2350.31
  text "Symbol" at 5611.35,3550.5 h61.95
  text "Quantity" at 6051.04,3550.5 h61.95
  text "Finished Hole Size" at 6612.91,3550.5 h61.95
  text "Plated" at 7775.07,3550.5 h61.95
  text "Hole Type" at 8214.77,3550.5 h61.95
  text "Drill Layer Pair" at 8850.56,3550.5 h61.95
  text "Hole Tolerance" at 10143.49,3550.5 h61.95
  text "240" at 6051.04,3421.44 h51.62
  text "7.87mil (0.200mm)" at 6612.91,3421.44 h51.62
  text "PTH" at 7775.07,3421.44 h51.62
  text "Round" at 8214.77,3421.44 h51.62
  text "Top Layer - Bottom Layer" at 8850.56,3421.44 h51.62
  text "1161" at 6051.04,3292.39 h51.62
  text "10.00mil (0.254mm)" at 6612.91,3292.39 h51.62
  text "PTH" at 7775.07,3292.39 h51.62
  text "Round" at 8214.77,3292.39 h51.62
  text "Top Layer - Bottom Layer" at 8850.56,3292.39 h51.62
  text "28" at 6051.04,3163.34 h51.62
  text "37.00mil (0.940mm)" at 6612.91,3163.34 h51.62
  text "PTH" at 7775.07,3163.34 h51.62
  text "Round" at 8214.77,3163.34 h51.62
  text "Top Layer - Bottom Layer" at 8850.56,3163.34 h51.62
  text "5" at 6051.04,3034.29 h51.62
  text "40.00mil (1.016mm)" at 6612.91,3034.29 h51.62
  text "PTH" at 7775.07,3034.29 h51.62
  text "Round" at 8214.77,3034.29 h51.62
  text "Top Layer - Bottom Layer" at 8850.56,3034.29 h51.62
  text "24" at 6051.04,2905.24 h51.62
  text "40.16mil (1.020mm)" at 6612.91,2905.24 h51.62
  text "PTH" at 7775.07,2905.24 h51.62
  text "Round" at 8214.77,2905.24 h51.62
  text "Top Layer - Bottom Layer" at 8850.56,2905.24 h51.62
  text "56" at 6051.04,2776.18 h51.62
  text "50.00mil (1.270mm)" at 6612.91,2776.18 h51.62
  text "PTH" at 7775.07,2776.18 h51.62
  text "Round" at 8214.77,2776.18 h51.62
  text "Top Layer - Bottom Layer" at 8850.56,2776.18 h51.62
  text "4" at 6051.04,2647.13 h51.62
  text "51.18mil (1.300mm)" at 6612.91,2647.13 h51.62
  text "PTH" at 7775.07,2647.13 h51.62
  text "Round" at 8214.77,2647.13 h51.62
  text "Top Layer - Bottom Layer" at 8850.56,2647.13 h51.62
  text "8" at 6051.04,2518.08 h51.62
  text "125.98mil (3.200mm)" at 6612.91,2518.08 h51.62
  text "PTH" at 7775.07,2518.08 h51.62
  text "Round" at 8214.77,2518.08 h51.62
  text "Top Layer - Bottom Layer" at 8850.56,2518.08 h51.62
  text "1526 Total" at 6051.04,2389.03 h51.62
  text ".Layer_Name" at 577,-858.49 h60
M17 Embedded Cavity:
  text ".Layer_Name" at 577,-858.49 h60
M18 Embedded Assembly:
  text ".Layer_Name" at 577,-858.49 h60
M19 Embedded Keepout:
  text ".Layer_Name" at 577,-858.49 h60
